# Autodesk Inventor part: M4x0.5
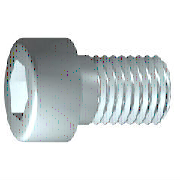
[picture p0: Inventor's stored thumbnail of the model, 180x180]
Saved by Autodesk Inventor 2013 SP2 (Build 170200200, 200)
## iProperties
IsCustomPart: 1
Company: 한국ATC센터
Created: 2014-10
Part Number: M4x0.5
Material: 강, 연강
Description: 6각머리 태핑 나사
Document SubType Name: Modeling
Standard: KS B 1003
Designer: 한국ATC센터
Standards Organization: KS
Language: ko-KR
Size Designation: M 4 x 16
Categories: <MemberInstance><Categories><Category DisplayName="조임쇠" InternalName="e4da775c-781d-43d5-af7c-5136215cf5a6" Mnemonic="FSTN"><Category DisplayName="볼트" InternalN
Density: 7.86 g/cm^3
Mass: 2.62973 g
Surface Area: 3.81119 cm^2
Volume: 0.334572 cm^3
Author: KYOUNG IL JANG
Revision Number: 1
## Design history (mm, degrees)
sketch "스케치1"
  geometry: L1 (-1, 0)-(16, 0); L2 (16, 0)-(16, 2); L3 (16, 2)-(1.75, 2); L4 (1.75, 2)-(1.32, 2); L5 (1.32, 2)-(0, 2); L6 (0, 2)-(0, 3.5); L7 (0, 3.5)-(-4, 3.5); L8 (-4, 3.5)-(-4, 1.732); L9 (-4, 1.732)-(-2, 1.732); L10 (-2, 1.732)-(-1, 0); L11 (-8, 0)-(20, 0) reference; L12 (0, -0.7)-(0, 4.2) reference; L13 (1.75, 2)-(0, 2)
  constraints: 22 end point, 6 parallel, 2 collinear, 2 perpendicular, 1 horizontal, 1 point on line
  dimensions: "d1" = 14.25 distance from line of L3.end L2 (= GEL); "d2" = 0.42952 distance of L4.end L3.end (computed from GAL); "d3" = 4 distance between parallel lines of L8 L6 (= KOH); "d4" = 2 distance of L8.end L9.end (= INTI); "d5" = 60 deg angle of L10 L1; "d6" = 4 diameter of L3 L1 (= GD); "d7" = 4 diameter of L5 L1 (= BDM); "d8" = 3.4641 diameter of L9 L1 (= 1.1547 x SW); "d9" = 7 diameter of L7 L1 (= KOD); "d26" = 16 distance between parallel lines of L12 L2 (= NLG)
revolve "본체" sketch "스케치1" stored, may be unused: angle "d10" = 90 deg
sketch "스케치2"
  geometry: L1 (0, -4.9)-(0, 4.9) reference; L2 (-4.9, 0)-(4.9, 0) reference; L3 (1.732, 0)-(0.866, -1.5); L4 (0.866, -1.5)-(-0.866, -1.5); L5 (-0.866, -1.5)-(-1.732, 0); L6 (-1.732, 0)-(-0.866, 1.5); L7 (-0.866, 1.5)-(0.866, 1.5); L8 (0.866, 1.5)-(1.732, 0); 2 further points
  constraints: 12 end point, 1 coincident, 1 horizontal alignment, 1 point on line, 12 other
extrude "슬롯" join sketch "스케치2" stored distance "d11" = 10; taper "d12" = 0 deg
workplane "Work Plane1"
fillet "Fillet2" dims "d30" = 0.1 (= R)
body "Solid1"
fillet "모깎기1" dims "d17" = 0.4 (= RR)
feature "스레드" dims "d13" = 14.25 (= GEL), "d14" = 0
chamfer "모따기1" distance "d15" = 0.42941 (= -0.5 x SPD + 0.5 x GD); stored, may be unused: second distance "d16" = 0.42941 (= GUL), angle "d27" = 45 deg
other parameters: "GD" = 4 (= NND) [user parameter; used in 2 equation terms], "NLG" = 16 [user parameter; used in 1 equation term], "GEL" = 14.25 [user parameter; used in 2 equation terms], "KOD" = 7 [user parameter; used in 1 equation term], "KOH" = 4 [user parameter; used in 1 equation term], "INTI" = 2 [user parameter; used in 1 equation term], "GAL" = 0.42941 (= 0.61345 x PTC) [user parameter; used in 1 equation term], "GUL" = 0.42941 (= 0.61345 x PTC) [user parameter; used in 1 equation term], "BDM" = 4 (= NND) [user parameter; used in 1 equation term], "SW" = 3 [user parameter; used in 2 equation terms], "RR" = 0.4 [user parameter; used in 1 equation term], "SPD" = 3.14117 (= NND - 1.2269 x PTC) [user parameter; used in 1 equation term], "d19" = 0, "d28" = 0, "d29" = 0, "R" = 0.1 [user parameter; used in 1 equation term], "PHH" = 0.2 [user parameter], "GD1" = 3.14117 (= THREADDIA - 1.2269 x PTC) [user parameter], "THREADDIA" = 4 [user parameter; used in 1 equation term], "FAWI" = 45 deg [user parameter], "TPU" = 14.28571 (computed from PTC) [user parameter], "PTC" = 0.7 [user parameter; used in 5 equation terms], "NND" = 4 [user parameter; used in 3 equation terms], "TOA" = 30 deg [user parameter], "E0" = 3.465 (= 1.155 x SW) [user parameter]
